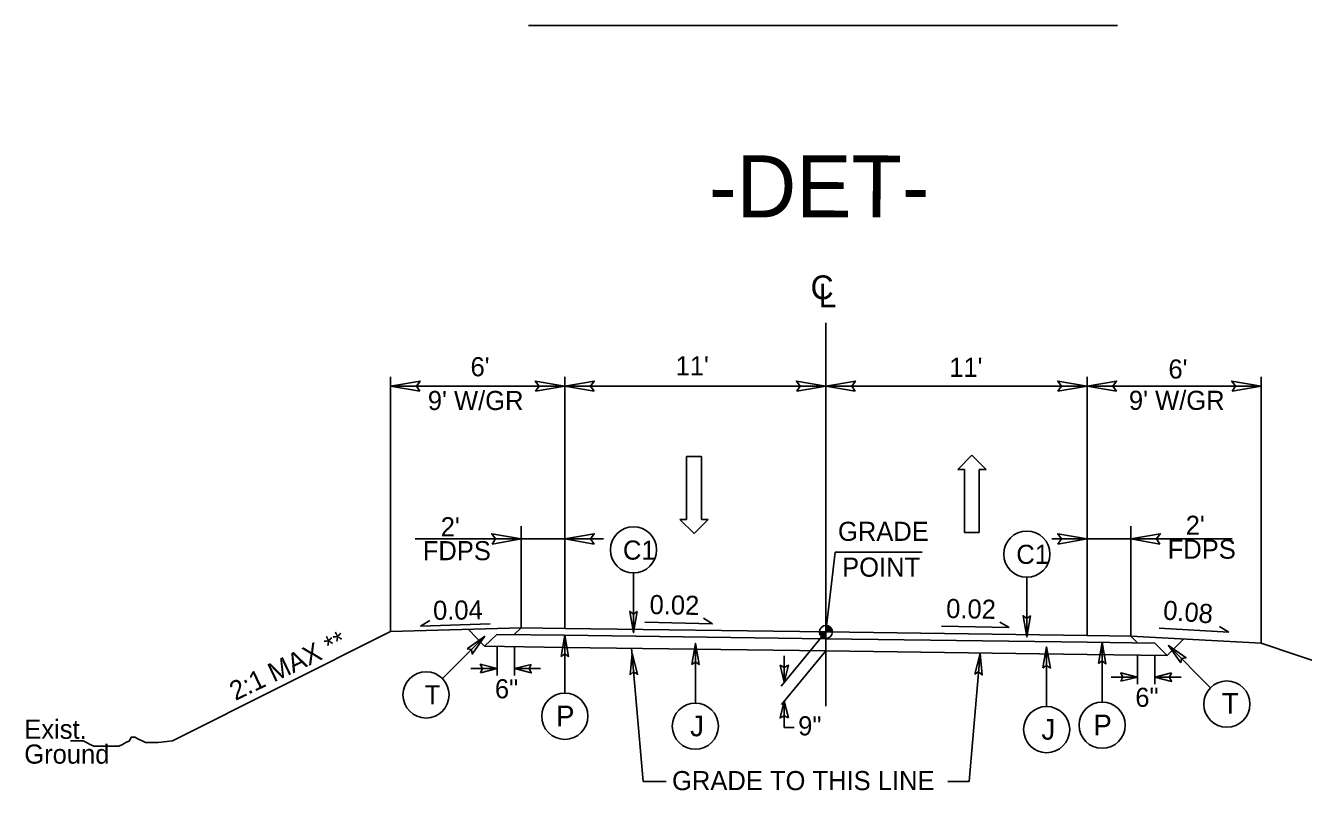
# Model space of a CAD drawing. Extents: x 1497225 to 1499181, y 579958 to 582278.
# Drawn here: x 1497802.8 to 1498271.3, y 580467.5 to 580747.7 of the extents above; entities that cross this region are included whole.
import ezdxf

# ---------------------------------------------------------------- set-up
doc = ezdxf.new("R2010")
doc.units = 0
for name, color, linetype in [('Old_Level_1', 7, 'Continuous'), ('Old_Level_11', 7, 'Continuous'), ('Old_Level_4', 7, 'Continuous'), ('Prop Dimension Text', 7, 'Continuous'), ('Typical ID Circle CELL', 7, 'Continuous'), ('Typical Terminator CELL', 7, 'Continuous'), ('Typical Text ID Circle CELL', 7, 'Continuous'), ('Typical Text Label CELL', 7, 'Continuous')]:
    doc.layers.add(name, color=color, linetype=linetype)

# ---------------------------------------------------------------- blocks, each defined once
blk = doc.blocks.new('TERMINATOR')
at = {"layer": 'Typical Terminator CELL'}
blk.add_lwpolyline([(-0.469, 0.081), (0, 0), (-0.471, -0.083), (-0.411, 0)], close=True, dxfattribs=at)

msp = doc.modelspace()

# ---------------------------------------------------------------- linework, layer by layer
at = {"layer": 'Old_Level_1'}
for p, q in [((1498096.23, 580498.33), (1498096.23, 580638.85)), ((1497936.62, 580525.64), (1497936.62, 580619.03)), ((1498000.47, 580526.8), (1498000.47, 580619.03)), ((1498191.99, 580524.25), (1498191.99, 580619.03)), ((1498255.84, 580521.37), (1498255.84, 580619.03)), ((1497936.62, 580615.59), (1498000.47, 580615.59)), ((1498000.47, 580615.59), (1498096.23, 580615.59)), ((1498096.23, 580615.59), (1498191.99, 580615.59)), ((1498191.99, 580615.59), (1498255.84, 580615.59)), ((1497984.51, 580527.01), (1497984.51, 580564.26)), ((1498207.95, 580524.03), (1498207.95, 580564.26)), ((1497945.65, 580559.6), (1498014.67, 580559.6)), ((1497984.51, 580559.6), (1498000.47, 580559.6)), ((1498179.04, 580559.6), (1498245.19, 580559.6)), ((1498191.99, 580559.6), (1498207.95, 580559.6)), ((1498096.23, 580525.52), (1498099.64, 580554.78)), ((1498099.64, 580554.78), (1498131.53, 580554.78)), ((1497947.54, 580527.71), (1497950.97, 580529.67)), ((1497947.54, 580527.71), (1497973.08, 580528.45)), ((1498054.66, 580528.56), (1498029.81, 580529.06)), ((1498054.66, 580528.56), (1498051.28, 580530.6)), ((1498096.23, 580525.52), (1498096.23, 580527.91)), ((1498163.39, 580527.13), (1498138.54, 580527.63)), ((1498163.39, 580527.13), (1498160.02, 580529.17)), ((1498240.56, 580527.53), (1498243.94, 580525.49)), ((1497936.62, 580525.64), (1497856.62, 580485.64)), ((1497936.56, 580525.64), (1497984.51, 580527.01)), ((1497965.13, 580526.46), (1497970.99, 580520.27)), ((1497970.99, 580520.27), (1497975.61, 580524.65)), ((1497975.61, 580524.65), (1498000.4, 580524.32)), ((1497981.92, 580524.57), (1497984.51, 580527.01)), ((1497984.51, 580527.01), (1498000.47, 580526.81)), ((1498000.4, 580524.32), (1498096.16, 580523.04)), ((1498000.47, 580526.81), (1498096.23, 580525.52)), ((1498096.23, 580525.52), (1498079.75, 580505.69)), ((1498093.85, 580525.52), (1498096.23, 580525.52)), ((1498191.99, 580524.25), (1498096.23, 580525.52)), ((1498098.61, 580525.52), (1498096.23, 580525.52)), ((1498096.23, 580523.14), (1498096.23, 580525.52)), ((1498096.23, 580525.52), (1498096.23, 580523.14)), ((1498191.99, 580521.77), (1498096.23, 580523.04)), ((1498207.95, 580524.03), (1498191.99, 580524.25)), ((1498255.84, 580521.37), (1498207.95, 580524.03)), ((1498207.95, 580524.03), (1498210.47, 580521.51)), ((1498218.42, 580526.86), (1498243.94, 580525.49)), ((1498227.31, 580522.95), (1498221.28, 580516.93)), ((1497970.99, 580520.27), (1498000.28, 580519.89)), ((1497975.67, 580509.54), (1497975.67, 580520.21)), ((1497981.99, 580509.54), (1497981.99, 580520.13)), ((1498000.28, 580519.89), (1498096.05, 580518.61)), ((1498029.22, 580470.78), (1498024.96, 580519.56)), ((1498096.23, 580518.61), (1498079.9, 580498.96)), ((1498191.99, 580517.33), (1498096.23, 580518.61)), ((1498216.79, 580521.43), (1498191.99, 580521.77)), ((1498221.28, 580516.93), (1498216.79, 580521.43)), ((1498342.06, 580492.63), (1498255.84, 580521.37)), ((1498080.95, 580507.15), (1498080.95, 580516.77)), ((1498152.81, 580517.66), (1498148.7, 580470.78)), ((1498221.28, 580516.93), (1498191.99, 580517.33)), ((1498210.47, 580506.41), (1498210.47, 580517.08)), ((1498216.79, 580506.41), (1498216.79, 580516.99)), ((1497975.67, 580512.11), (1497966.05, 580512.11)), ((1497981.99, 580512.11), (1497991.62, 580512.11)), ((1498210.47, 580508.98), (1498200.84, 580508.98)), ((1498216.79, 580508.98), (1498226.41, 580508.98)), ((1498080.95, 580500.23), (1498080.95, 580490.56)), ((1498084.51, 580490.56), (1498080.95, 580490.56)), ((1498037.61, 580470.78), (1498029.22, 580470.78)), ((1498148.7, 580470.78), (1498140.91, 580470.78))]:
    msp.add_line(p, q, dxfattribs=at)
for points in [[(1498096.25, 580527.91), (1498096.25, 580527.91), (1498096.25, 580525.52)], [(1498096.3, 580527.91), (1498096.3, 580525.52)], [(1498096.35, 580527.9), (1498096.35, 580525.52)], [(1498096.39, 580527.9), (1498096.39, 580525.52)], [(1498096.44, 580527.9), (1498096.44, 580525.52)], [(1498096.49, 580527.89), (1498096.49, 580525.52)], [(1498096.54, 580527.89), (1498096.54, 580525.52)], [(1498096.59, 580527.88), (1498096.59, 580525.52)], [(1498096.63, 580527.88), (1498096.63, 580525.52)], [(1498096.68, 580527.86), (1498096.68, 580525.52)], [(1498096.73, 580527.85), (1498096.73, 580525.52)], [(1498096.78, 580527.84), (1498096.78, 580525.52)], [(1498096.82, 580527.83), (1498096.82, 580525.52)], [(1498096.87, 580527.82), (1498096.87, 580525.52)], [(1498096.92, 580527.81), (1498096.92, 580525.52)], [(1498096.97, 580527.79), (1498096.97, 580525.52)], [(1498097.01, 580527.77), (1498097.01, 580525.52)], [(1498097.06, 580527.76), (1498097.06, 580525.52)], [(1498097.11, 580527.74), (1498097.11, 580525.52)], [(1498097.16, 580527.72), (1498097.16, 580525.52)], [(1498097.2, 580527.69), (1498097.2, 580525.52)], [(1498097.25, 580527.67), (1498097.25, 580525.52)], [(1498097.3, 580527.65), (1498097.3, 580525.52)], [(1498097.35, 580527.63), (1498097.35, 580525.52)], [(1498097.4, 580527.6), (1498097.4, 580525.52)], [(1498097.44, 580527.57), (1498097.44, 580525.52)], [(1498097.49, 580527.55), (1498097.49, 580525.52)], [(1498097.54, 580527.52), (1498097.54, 580525.52)], [(1498097.59, 580527.48), (1498097.59, 580525.52)], [(1498097.63, 580527.45), (1498097.63, 580525.52)], [(1498093.86, 580525.52), (1498093.86, 580525.27)], [(1498093.91, 580525.52), (1498093.91, 580524.98)], [(1498093.95, 580525.52), (1498093.95, 580524.82)], [(1498094, 580525.52), (1498094, 580524.67)], [(1498094.05, 580525.52), (1498094.05, 580524.56)], [(1498094.1, 580525.52), (1498094.1, 580524.46)], [(1498094.14, 580525.52), (1498094.14, 580524.37)], [(1498094.19, 580525.52), (1498094.19, 580524.29)], [(1498094.24, 580525.52), (1498094.24, 580524.21)], [(1498094.29, 580525.52), (1498094.29, 580524.14)], [(1498094.34, 580525.52), (1498094.34, 580524.08)], [(1498094.38, 580525.52), (1498094.38, 580524.02)], [(1498094.43, 580525.52), (1498094.43, 580523.96)], [(1498094.48, 580525.52), (1498094.48, 580523.91)], [(1498094.53, 580525.52), (1498094.53, 580523.86)], [(1498094.57, 580525.52), (1498094.57, 580523.81)], [(1498094.62, 580525.52), (1498094.62, 580523.77)], [(1498094.67, 580525.52), (1498094.67, 580523.72)], [(1498094.72, 580525.52), (1498094.72, 580523.68)], [(1498094.76, 580525.52), (1498094.76, 580523.65)], [(1498094.81, 580525.52), (1498094.81, 580523.61)], [(1498094.86, 580525.52), (1498094.86, 580523.58)], [(1498094.91, 580525.52), (1498094.91, 580523.54)], [(1498094.95, 580525.52), (1498094.95, 580523.51)], [(1498095, 580525.52), (1498095, 580523.48)], [(1498095.05, 580525.52), (1498095.05, 580523.45)], [(1498095.1, 580525.52), (1498095.1, 580523.43)], [(1498095.15, 580525.52), (1498095.15, 580523.4)], [(1498095.19, 580525.52), (1498095.19, 580523.38)], [(1498095.24, 580525.52), (1498095.24, 580523.36)], [(1498095.29, 580525.52), (1498095.29, 580523.34)], [(1498095.34, 580525.52), (1498095.34, 580523.32)], [(1498095.38, 580525.52), (1498095.38, 580523.3)], [(1498095.43, 580525.52), (1498095.43, 580523.28)], [(1498095.48, 580525.52), (1498095.48, 580523.26)], [(1498095.53, 580525.52), (1498095.53, 580523.25)], [(1498095.57, 580525.52), (1498095.57, 580523.24)], [(1498095.62, 580525.52), (1498095.62, 580523.22)], [(1498095.67, 580525.52), (1498095.67, 580523.21)], [(1498095.72, 580525.52), (1498095.72, 580523.2)], [(1498095.76, 580525.52), (1498095.76, 580523.19)], [(1498095.81, 580525.52), (1498095.81, 580523.18)], [(1498095.86, 580525.52), (1498095.86, 580523.17)], [(1498095.91, 580525.52), (1498095.91, 580523.16)], [(1498095.96, 580525.52), (1498095.96, 580523.16)], [(1498096, 580525.52), (1498096, 580523.15)], [(1498096.05, 580525.52), (1498096.05, 580523.15)], [(1498096.1, 580525.52), (1498096.1, 580523.15)], [(1498096.15, 580525.52), (1498096.15, 580523.14)], [(1498096.19, 580525.52), (1498096.19, 580523.14), (1498096.19, 580523.14)], [(1498097.68, 580527.41), (1498097.68, 580525.52)], [(1498097.73, 580527.38), (1498097.73, 580525.52)], [(1498097.78, 580527.34), (1498097.78, 580525.52)], [(1498097.82, 580527.29), (1498097.82, 580525.52)], [(1498097.87, 580527.25), (1498097.87, 580525.52)], [(1498097.92, 580527.2), (1498097.92, 580525.52)], [(1498097.97, 580527.16), (1498097.97, 580525.52)], [(1498098.01, 580527.1), (1498098.01, 580525.52)], [(1498098.06, 580527.04), (1498098.06, 580525.52)], [(1498098.11, 580526.99), (1498098.11, 580525.52)], [(1498098.16, 580526.92), (1498098.16, 580525.52)], [(1498098.21, 580526.85), (1498098.21, 580525.52)], [(1498098.25, 580526.78), (1498098.25, 580525.52)], [(1498098.3, 580526.7), (1498098.3, 580525.52)], [(1498098.35, 580526.62), (1498098.35, 580525.52)], [(1498098.4, 580526.51), (1498098.4, 580525.52)], [(1498098.44, 580526.4), (1498098.44, 580525.52)], [(1498098.49, 580526.27), (1498098.49, 580525.52)], [(1498098.54, 580526.11), (1498098.54, 580525.52)], [(1498098.59, 580525.86), (1498098.59, 580525.52)], [(1497856.62, 580485.64), (1497851.37, 580484.98), (1497850.06, 580484.98), (1497848.09, 580484.98), (1497846.78, 580484.98), (1497845.47, 580485.64), (1497844.16, 580486.29), (1497842.85, 580486.95), (1497841.54, 580486.95), (1497840.88, 580485.64), (1497839.57, 580484.98), (1497838.26, 580484.33), (1497836.94, 580483.67), (1497835.63, 580483.67), (1497834.32, 580483.67), (1497833.01, 580483.67), (1497831.7, 580483.67), (1497830.39, 580483.67), (1497829.08, 580483.67), (1497827.77, 580483.67), (1497826.45, 580484.33), (1497825.14, 580484.98), (1497823.83, 580485.64), (1497821.86, 580485.64), (1497820.55, 580485.64), (1497819.24, 580485.64)]]:
    msp.add_lwpolyline(points, dxfattribs=at)
msp.add_circle((1498096.23, 580525.53), 2.38, dxfattribs=at)
for start, end in [(359.9905, 89.9905), (179.9905, 269.9905)]:
    msp.add_arc((1498096.23, 580525.53), 2.38, start, end, dxfattribs=at)
at = {"layer": 'Old_Level_11'}
for points in [[(1497947.34, 580613.7), (1497936.62, 580615.59), (1497947.43, 580617.47), (1497946.05, 580615.59)], [(1497989.74, 580613.7), (1498000.47, 580615.59), (1497989.66, 580617.47), (1497991.03, 580615.59)], [(1498011.19, 580613.7), (1498000.47, 580615.59), (1498011.28, 580617.47), (1498009.9, 580615.59)], [(1498085.5, 580613.7), (1498096.23, 580615.59), (1498085.42, 580617.47), (1498086.79, 580615.59)], [(1498106.96, 580613.7), (1498096.23, 580615.59), (1498107.04, 580617.47), (1498105.67, 580615.59)], [(1498181.27, 580613.7), (1498191.99, 580615.59), (1498181.18, 580617.47), (1498182.56, 580615.59)], [(1498202.72, 580613.7), (1498191.99, 580615.59), (1498202.8, 580617.47), (1498201.43, 580615.59)], [(1498245.12, 580613.7), (1498255.84, 580615.59), (1498245.03, 580617.47), (1498246.41, 580615.59)], [(1497973.78, 580557.71), (1497984.51, 580559.6), (1497973.7, 580561.49), (1497975.07, 580559.6)], [(1498011.19, 580557.71), (1498000.47, 580559.6), (1498011.28, 580561.49), (1498009.9, 580559.6)], [(1498181.27, 580557.71), (1498191.99, 580559.6), (1498181.18, 580561.49), (1498182.56, 580559.6)], [(1498218.68, 580557.71), (1498207.95, 580559.6), (1498218.76, 580561.49), (1498217.39, 580559.6)]]:
    msp.add_lwpolyline(points, close=True, dxfattribs=at)
at = {"layer": 'Old_Level_4'}
for p, q in [((1498045.09, 580566.75), (1498045.09, 580589.85)), ((1498045.09, 580589.85), (1498050.54, 580589.85)), ((1498050.54, 580589.85), (1498050.54, 580566.75)), ((1498144.53, 580585.05), (1498149.65, 580590.25)), ((1498149.65, 580590.25), (1498154.93, 580585.05)), ((1498147.01, 580585.05), (1498144.53, 580585.05)), ((1498147.01, 580561.95), (1498147.01, 580585.05)), ((1498154.93, 580585.05), (1498152.45, 580585.05)), ((1498152.45, 580585.05), (1498152.45, 580561.95)), ((1498047.9, 580561.55), (1498042.62, 580566.75)), ((1498042.62, 580566.75), (1498045.09, 580566.75)), ((1498053.01, 580566.75), (1498047.9, 580561.55)), ((1498050.54, 580566.75), (1498053.01, 580566.75)), ((1498152.45, 580561.95), (1498147.01, 580561.95))]:
    msp.add_line(p, q, dxfattribs=at)
for points in [[(1498024.47, 580509.84), (1498025.12, 580517.66), (1498027.17, 580510.03), (1498025.71, 580510.9)], [(1498150.81, 580510.07), (1498152.81, 580517.66), (1498153.5, 580509.79), (1498152.21, 580510.9)]]:
    msp.add_lwpolyline(points, close=True, dxfattribs=at)
at = {"layer": 'Typical ID Circle CELL'}
for p, q in [((1498025.66, 580547.15), (1498025.66, 580525.28)), ((1498169.89, 580545.59), (1498169.89, 580523.71)), ((1497955.57, 580508.44), (1497971.04, 580523.91)), ((1498000.47, 580503.11), (1498000.47, 580524.32)), ((1498048.33, 580499.46), (1498048.33, 580521.33)), ((1498177.12, 580498.21), (1498177.12, 580520.08)), ((1498197.49, 580499.82), (1498197.49, 580521.69)), ((1498237.24, 580505.1), (1498221.77, 580520.56))]:
    msp.add_line(p, q, dxfattribs=at)
for centre in [(1498025.66, 580555.61), (1498169.89, 580554.05), (1497949.59, 580502.46), (1498243.22, 580499.11), (1498000.47, 580494.65), (1498048.33, 580491), (1498197.49, 580491.36), (1498177.12, 580489.75)]:
    msp.add_circle(centre, 8.46, dxfattribs=at)
at = {"layer": 'Typical Terminator CELL'}
for points in [[(1498026.99, 580533.01), (1498025.66, 580525.28), (1498024.29, 580533.05), (1498025.66, 580532.06)], [(1498171.22, 580531.45), (1498169.89, 580523.71), (1498168.51, 580531.49), (1498169.89, 580530.5)], [(1497964.63, 580519.38), (1497971.04, 580523.91), (1497966.51, 580517.44), (1497966.24, 580519.11)], [(1497999.14, 580516.59), (1498000.47, 580524.32), (1498001.84, 580516.55), (1498000.47, 580517.54)], [(1498047, 580513.6), (1498048.33, 580521.33), (1498049.71, 580513.56), (1498048.33, 580514.55)], [(1498175.79, 580512.35), (1498177.12, 580520.08), (1498178.5, 580512.31), (1498177.12, 580513.29)], [(1498196.16, 580513.96), (1498197.49, 580521.69), (1498198.87, 580513.91), (1498197.49, 580514.9)], [(1498226.29, 580514.16), (1498221.77, 580520.56), (1498228.24, 580516.04), (1498226.57, 580515.77)]]:
    msp.add_lwpolyline(points, close=True, dxfattribs=at)
at = {"layer": 'Typical Text Label CELL'}
msp.add_line((1497987.11, 580747.71), (1498203.16, 580747.71), dxfattribs=at)

# ---------------------------------------------------------------- block references
at = {"layer": 'Old_Level_4', "xscale": 13.123011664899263, "yscale": -18.835616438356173}
for p, rotation in [((1497975.67, 580512.11), 3.946795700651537e-12), ((1497981.99, 580512.11), -179.99999999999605), ((1498080.95, 580507.15), -89.99999999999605), ((1498210.47, 580508.98), 3.946795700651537e-12), ((1498216.79, 580508.98), -179.99999999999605), ((1498080.95, 580500.23), 90.00000000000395)]:
    msp.add_blockref('TERMINATOR', p, dxfattribs=dict(at, rotation=rotation))

# ---------------------------------------------------------------- texts
at = {"layer": 'Old_Level_1'}
for s, height, rotation, p in [('-DET-', 22.68, 359.9492, (1498053.32, 580677.48)), ('L', 8.73, 359.9469, (1498093.51, 580644.46)), ('0.04', 7, 0.6422, (1497952.21, 580529.94)), ('0.02', 7, 358.8543, (1498031.5, 580532.11)), ('0.02', 7, 358.8543, (1498140.24, 580530.67)), ('0.08', 7, 355.2385, (1498219.64, 580530.12)), ('2:1 MAX **', 7, 25.5705, (1497879.69, 580500.23)), ('Exist.', 7, 359.9492, (1497802.3, 580486.39)), ('Ground', 7, 359.9492, (1497802.29, 580477.29))]:
    msp.add_text(s, height=height, rotation=rotation, dxfattribs=at).set_placement(p)
for s, height, p in [('C', 8.73, (1498090.6, 580647.44)), ("6'", 7, (1497965.9, 580619.21)), ("11'", 7, (1498041.09, 580619.54)), ("11'", 7, (1498141.42, 580619)), ("6'", 7, (1498221.79, 580618.38)), ("9' W/GR", 7, (1497950.26, 580606.84)), ("9' W/GR", 7, (1498207.3, 580606.9)), ("2'", 7, (1497954.99, 580560.57)), ("2'", 7, (1498228.11, 580561.12)), ('FDPS', 7, (1497948.4, 580551.82)), ('FDPS', 7, (1498221.52, 580552.37)), ('GRADE TO THIS LINE', 7, (1498039.8, 580467.57))]:
    msp.add_text(s, height=height, dxfattribs=at).set_placement(p)
at = {"layer": 'Old_Level_4'}
for s, p in [('6"', (1497974.85, 580501.22)), ('6"', (1498209.64, 580498.09)), ('9"', (1498086.04, 580487.63))]:
    msp.add_text(s, height=7, rotation=360, dxfattribs=at).set_placement(p)
at = {"layer": 'Prop Dimension Text'}
for s, p in [('GRADE', (1498100.63, 580558.91)), ('POINT', (1498102.16, 580545.79))]:
    msp.add_text(s, height=7, rotation=0.0001, dxfattribs=at).set_placement(p)
at = {"layer": 'Typical Text ID Circle CELL'}
for s, height, p in [('C1', 7, (1498021.8, 580552.03)), ('C1', 7, (1498166.02, 580550.47)), ('T', 7, (1497949.12, 580498.97)), ('T', 7.58, (1498241.35, 580495.63)), ('P', 7.58, (1497997.24, 580490.96)), ('J', 7.58, (1498046.42, 580487.31)), ('P', 7.58, (1498194.26, 580487.66)), ('J', 7.58, (1498175.21, 580486.06))]:
    msp.add_text(s, height=height, dxfattribs=at).set_placement(p)

doc.saveas('drawing.dxf')
